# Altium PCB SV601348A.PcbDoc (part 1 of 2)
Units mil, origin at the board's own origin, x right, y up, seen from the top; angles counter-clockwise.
Board outline 3650 x 3650 mil, 6 copper layers (Top Layer, MidLayer1, MidLayer2, MidLayer3, MidLayer4, Bottom Layer), stack 60.8 mil thick; 122 components, 45 nets, 333 pads, 436 vias.
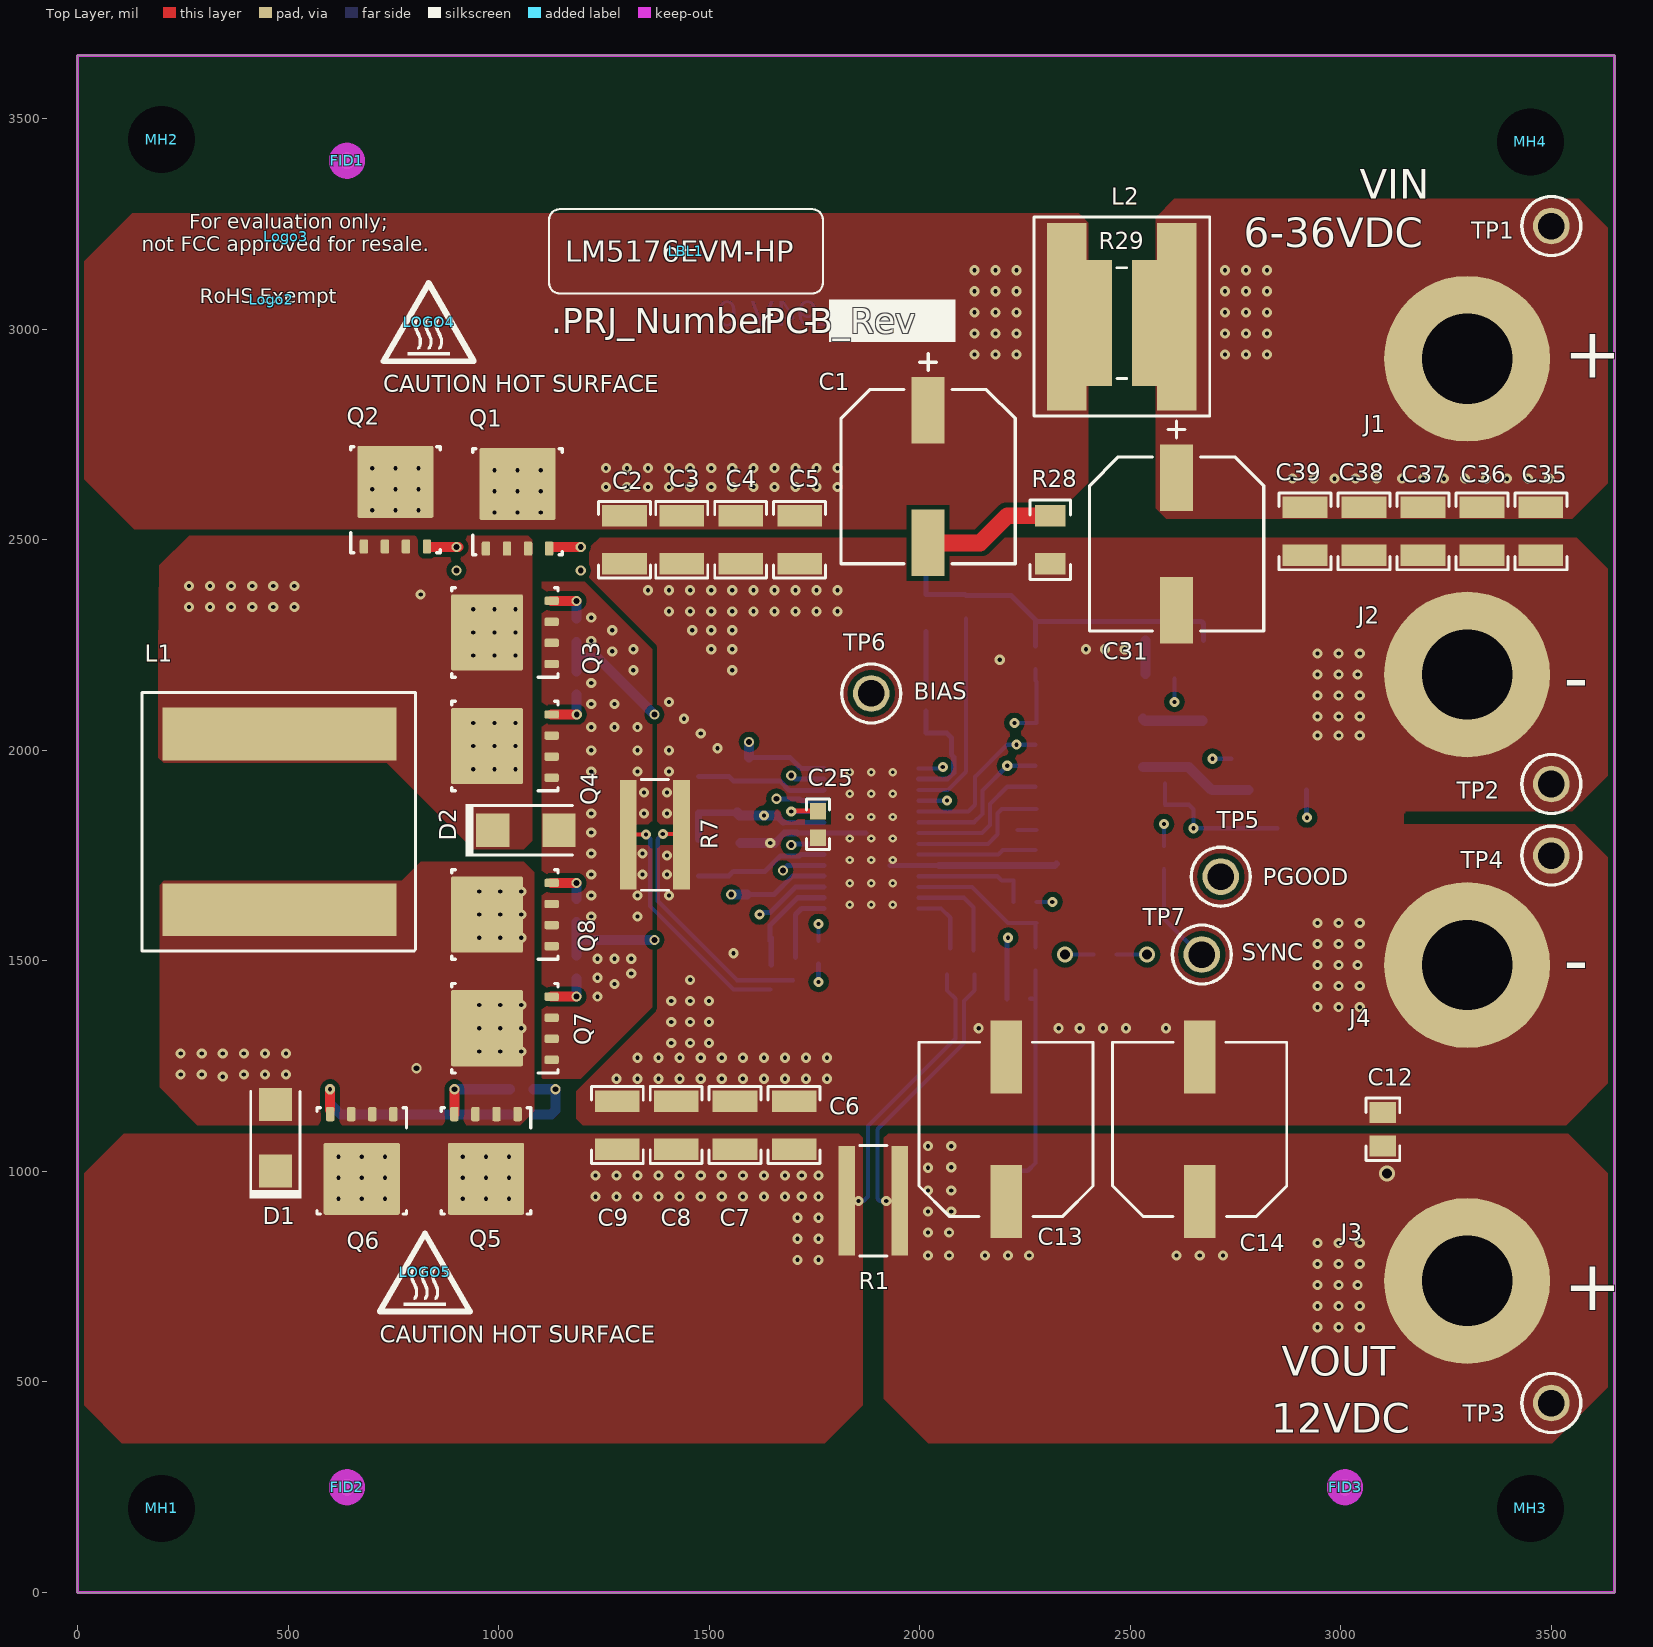
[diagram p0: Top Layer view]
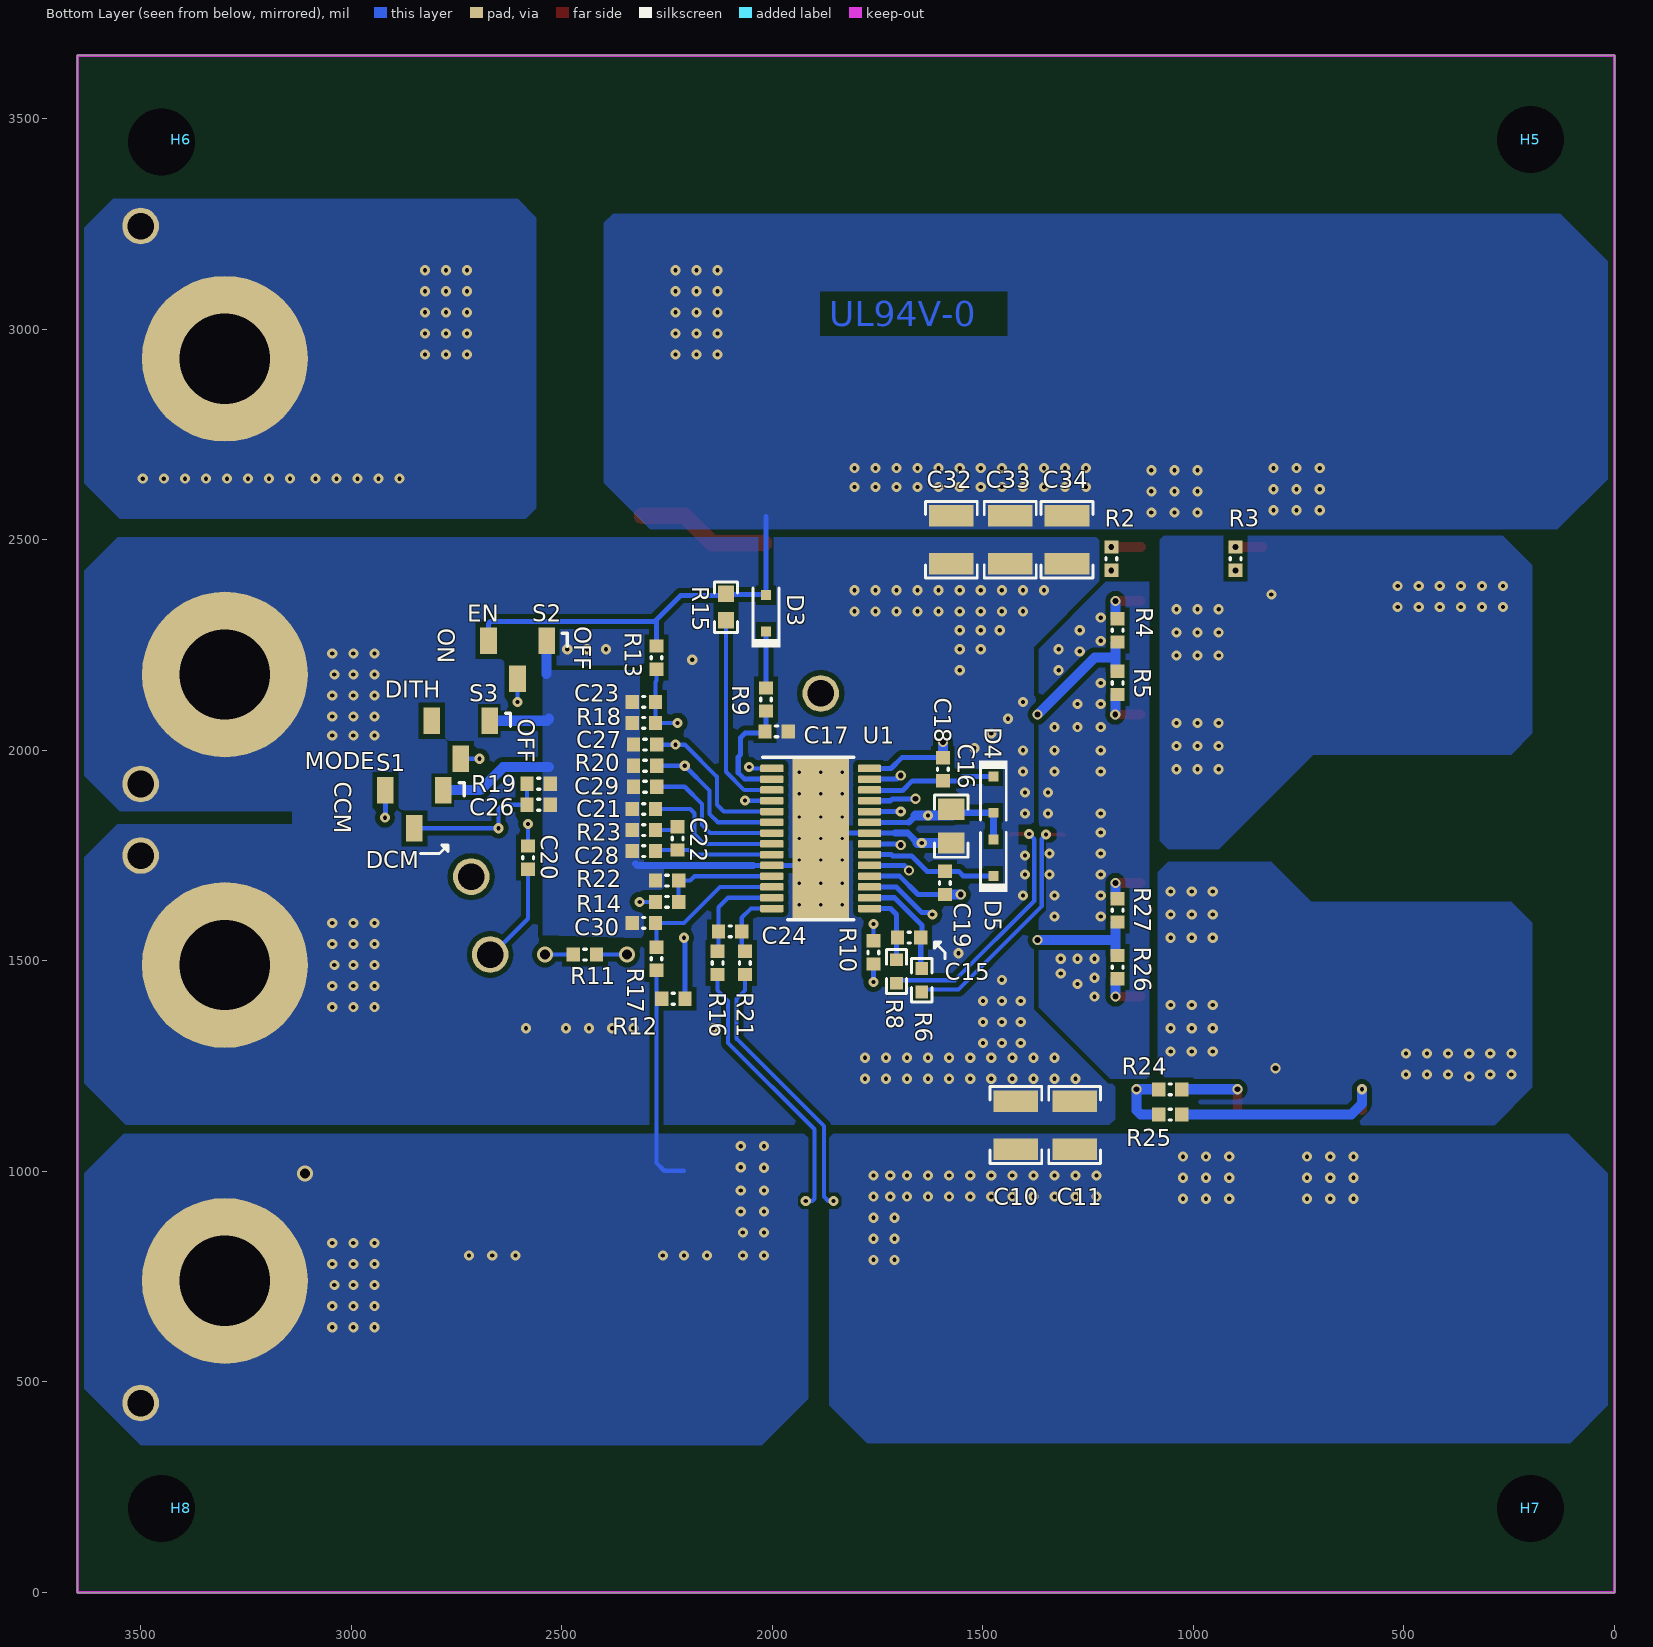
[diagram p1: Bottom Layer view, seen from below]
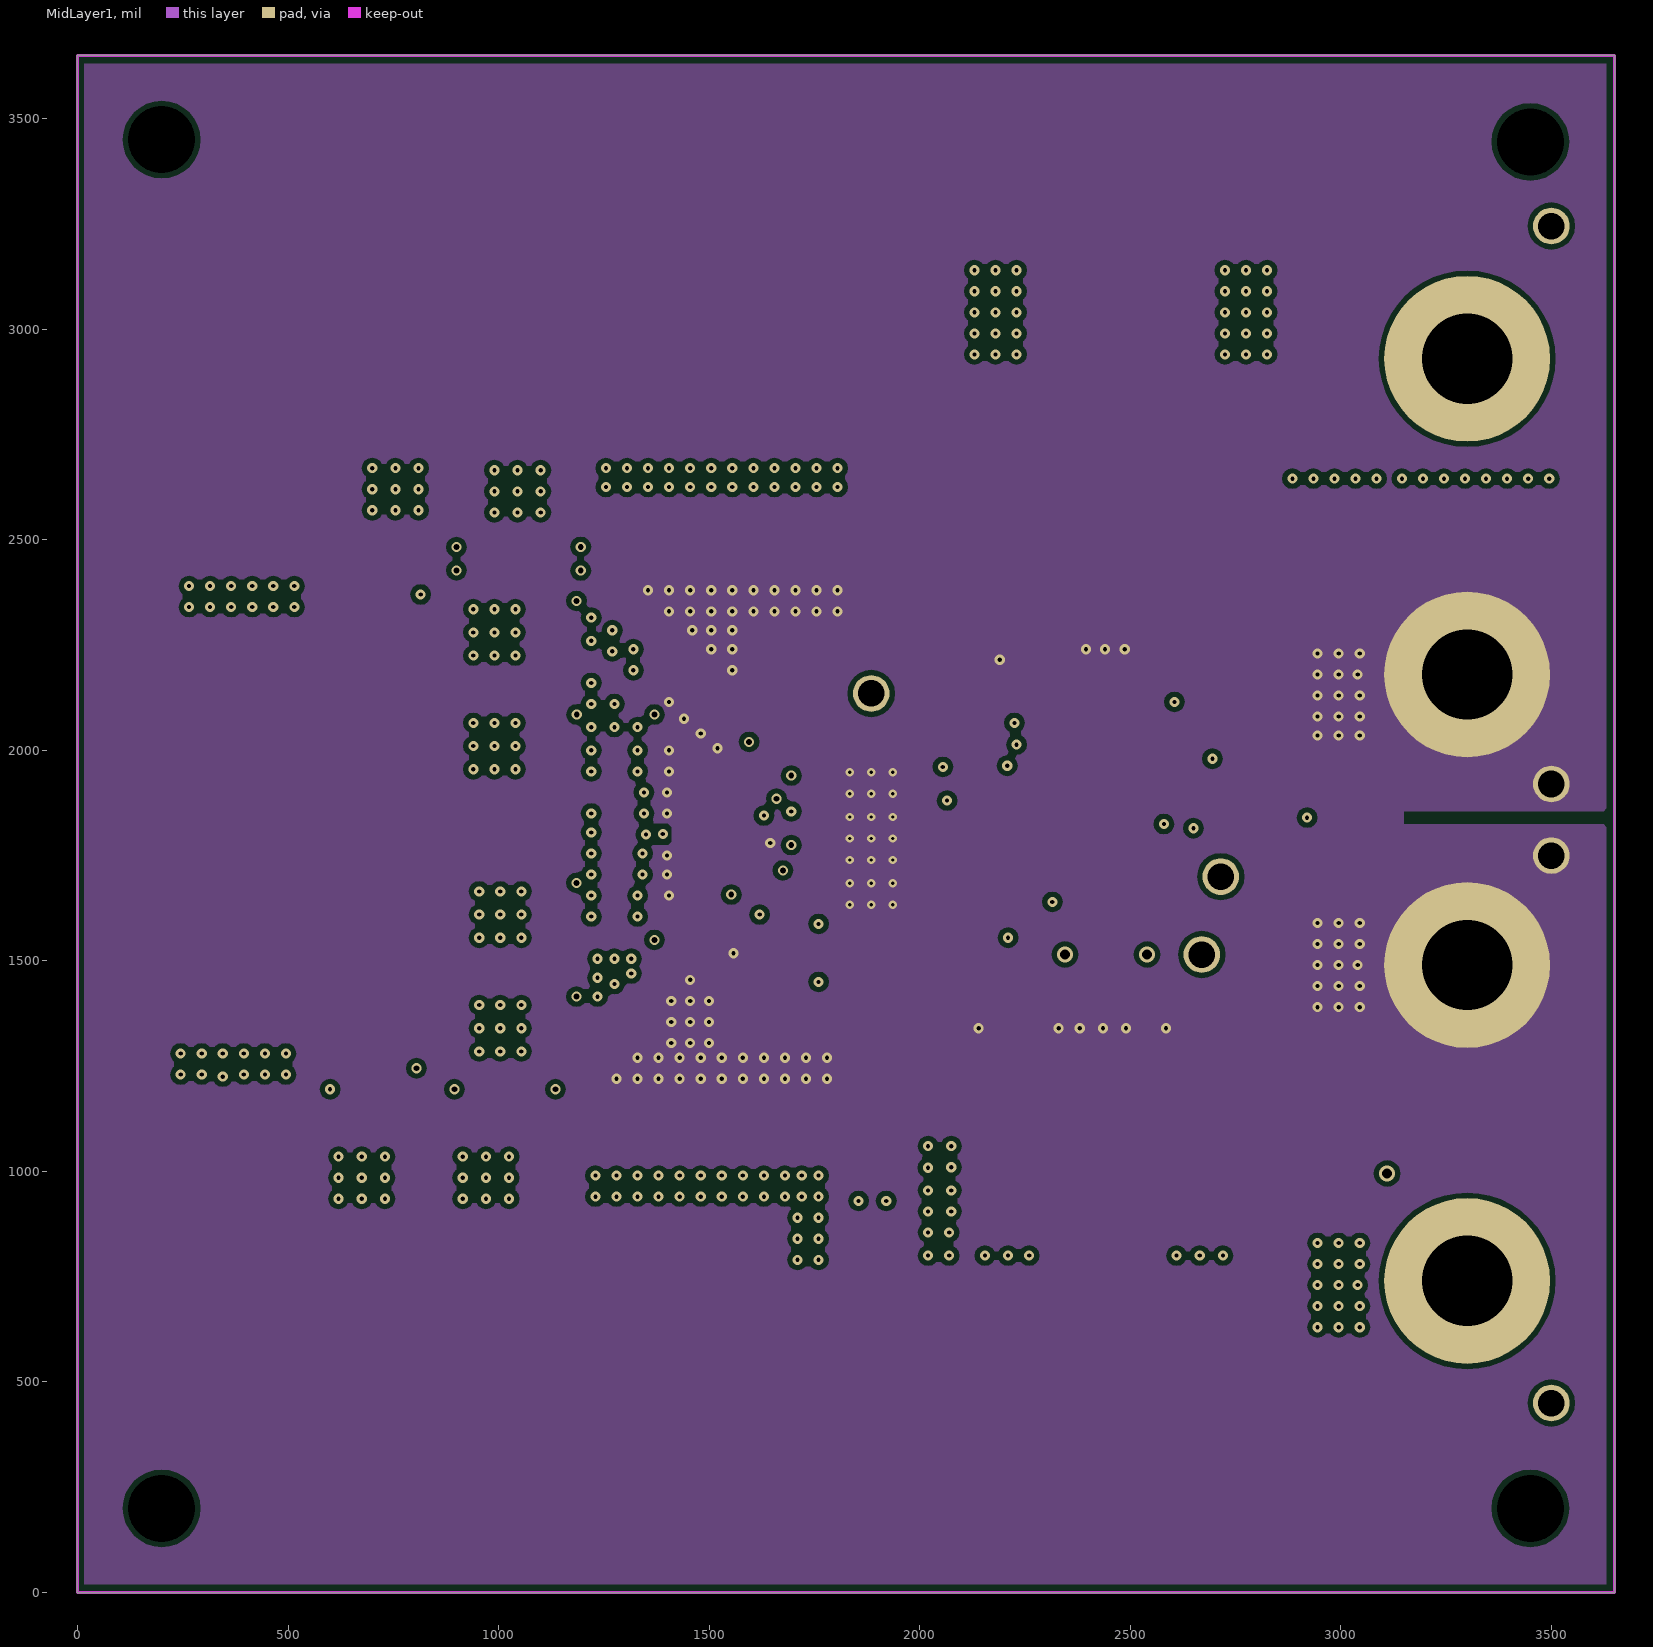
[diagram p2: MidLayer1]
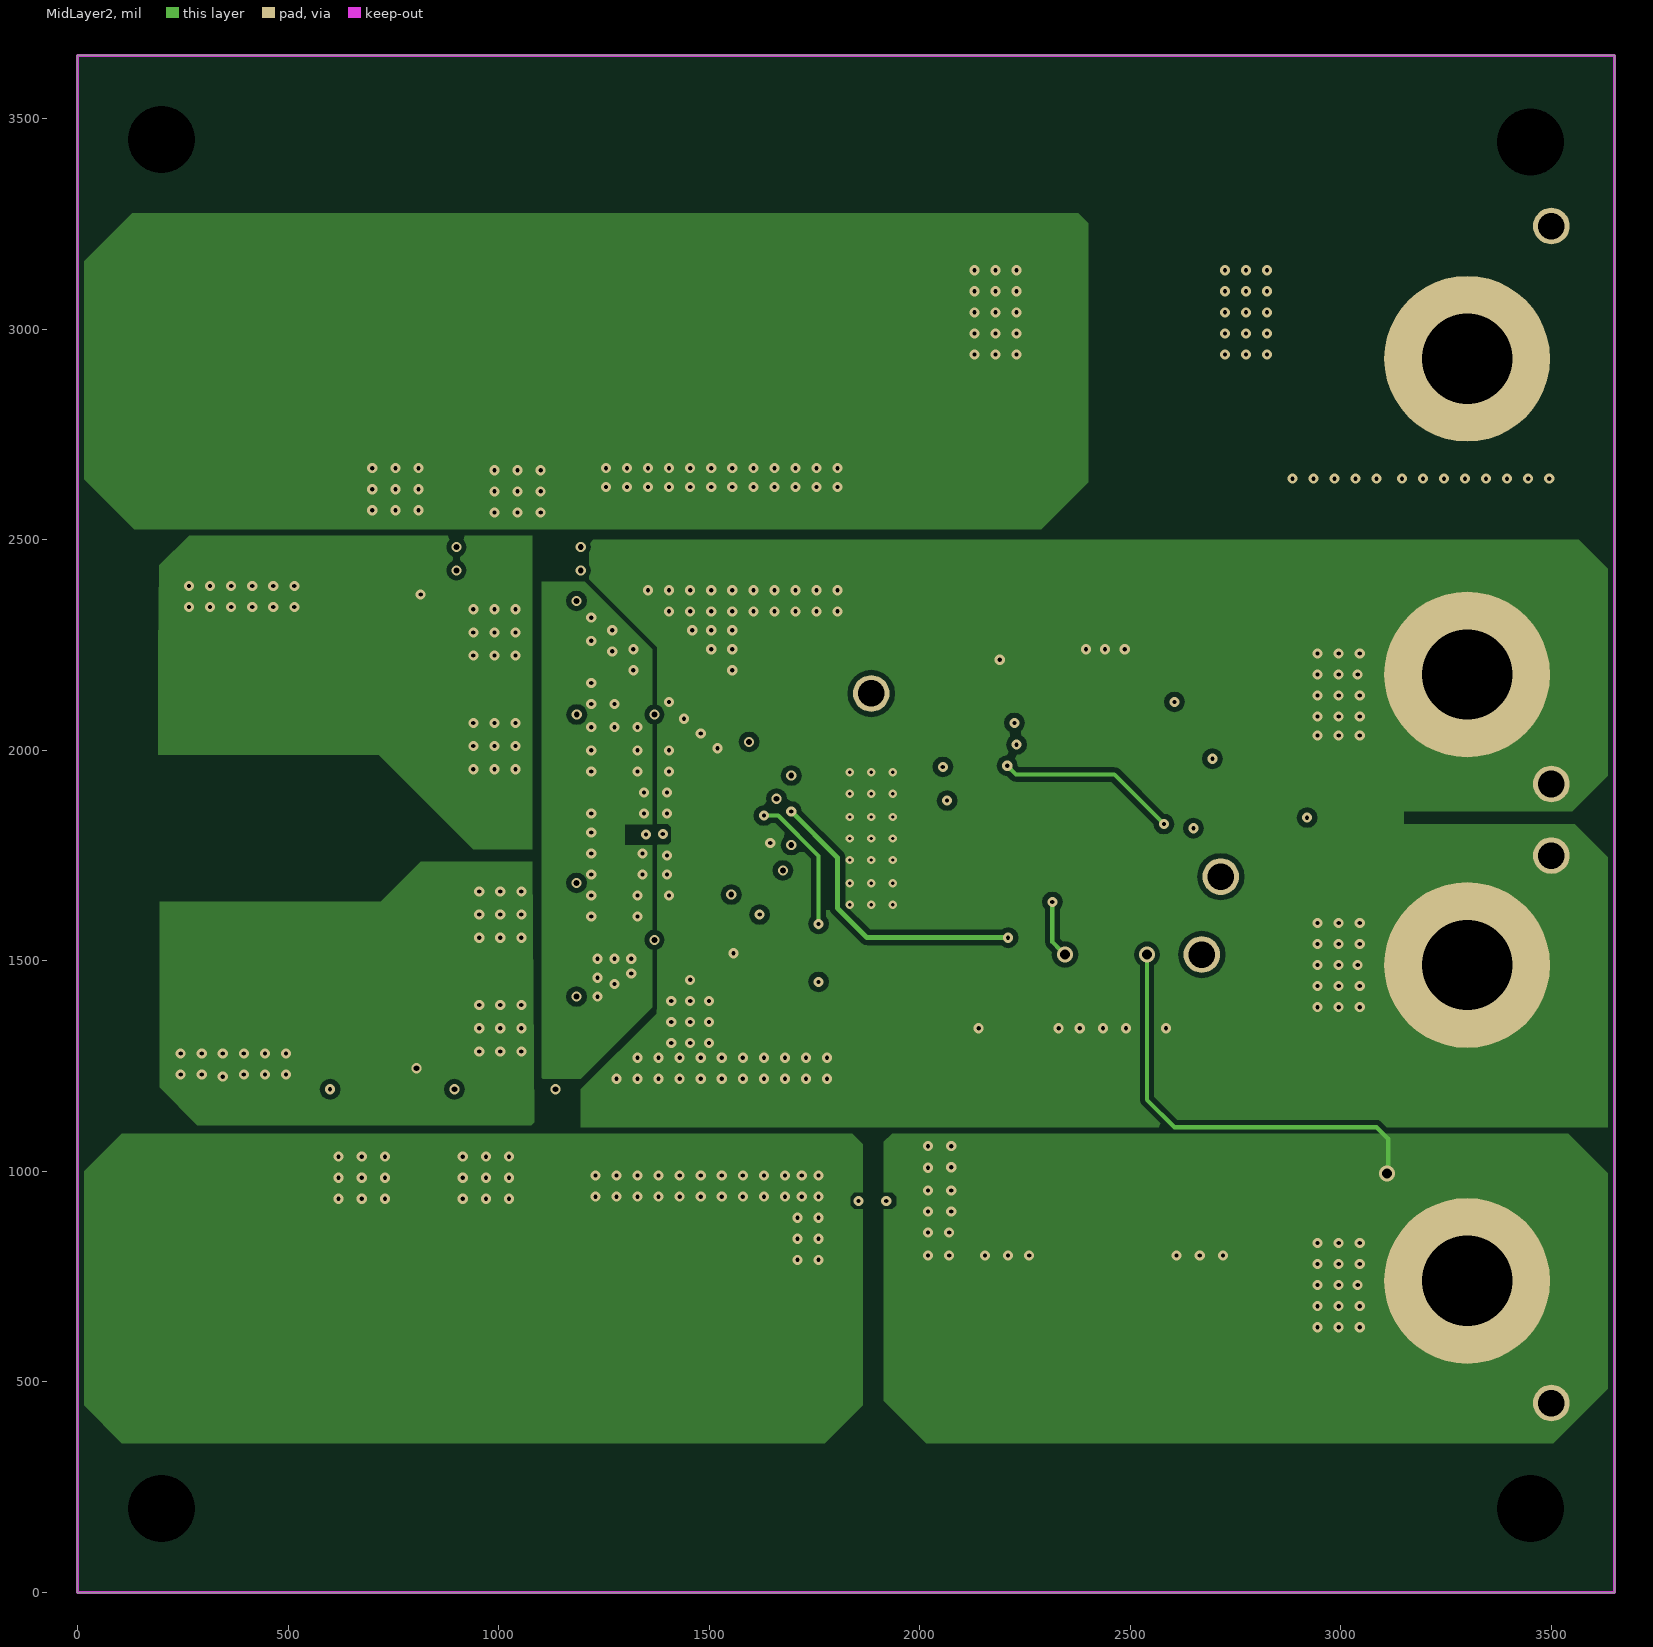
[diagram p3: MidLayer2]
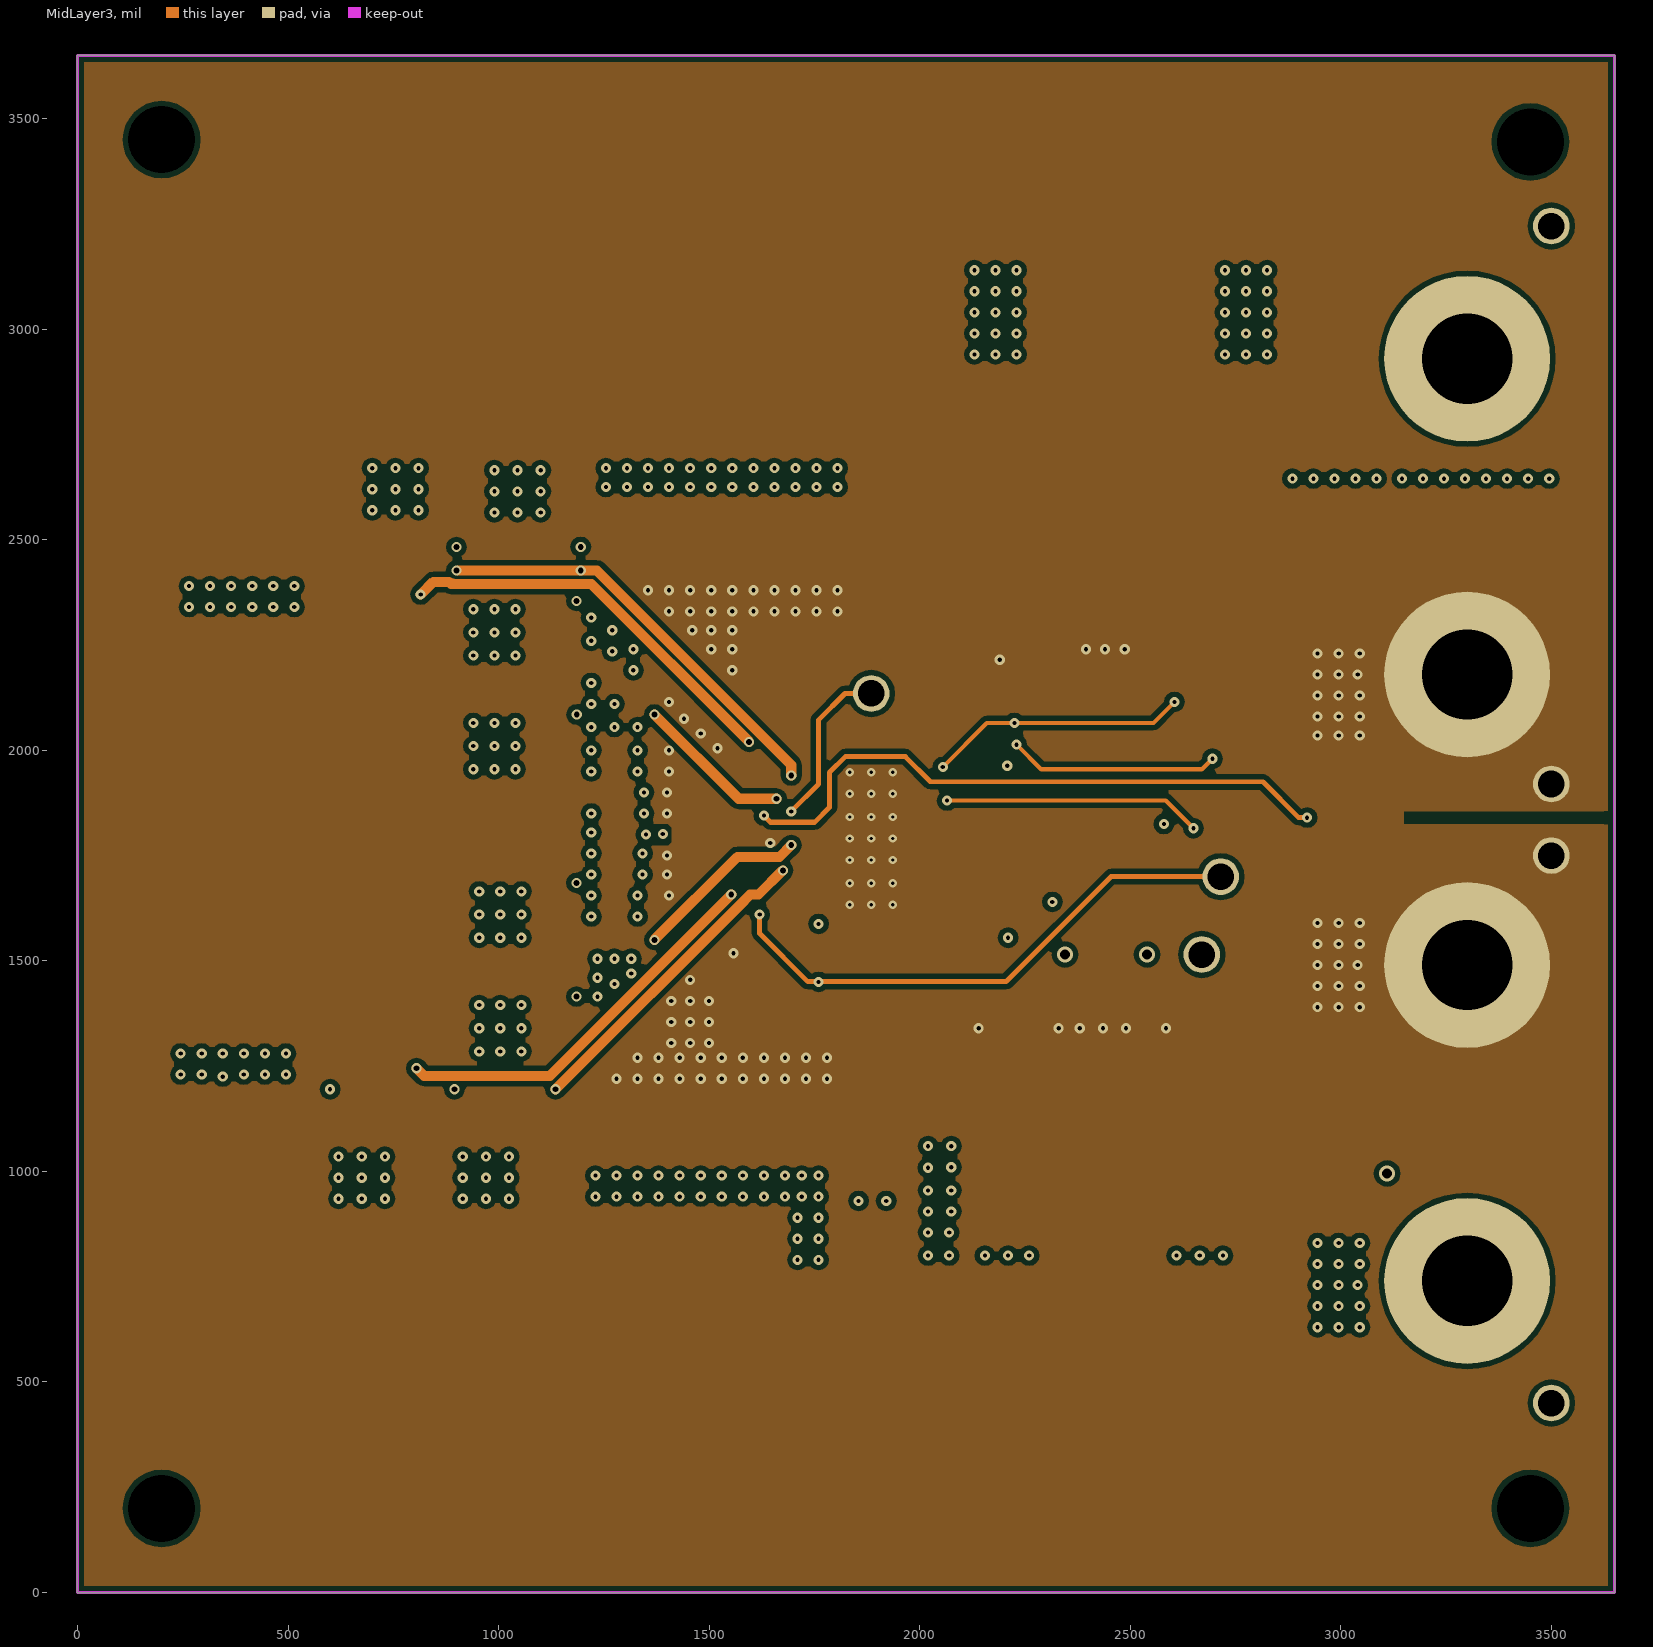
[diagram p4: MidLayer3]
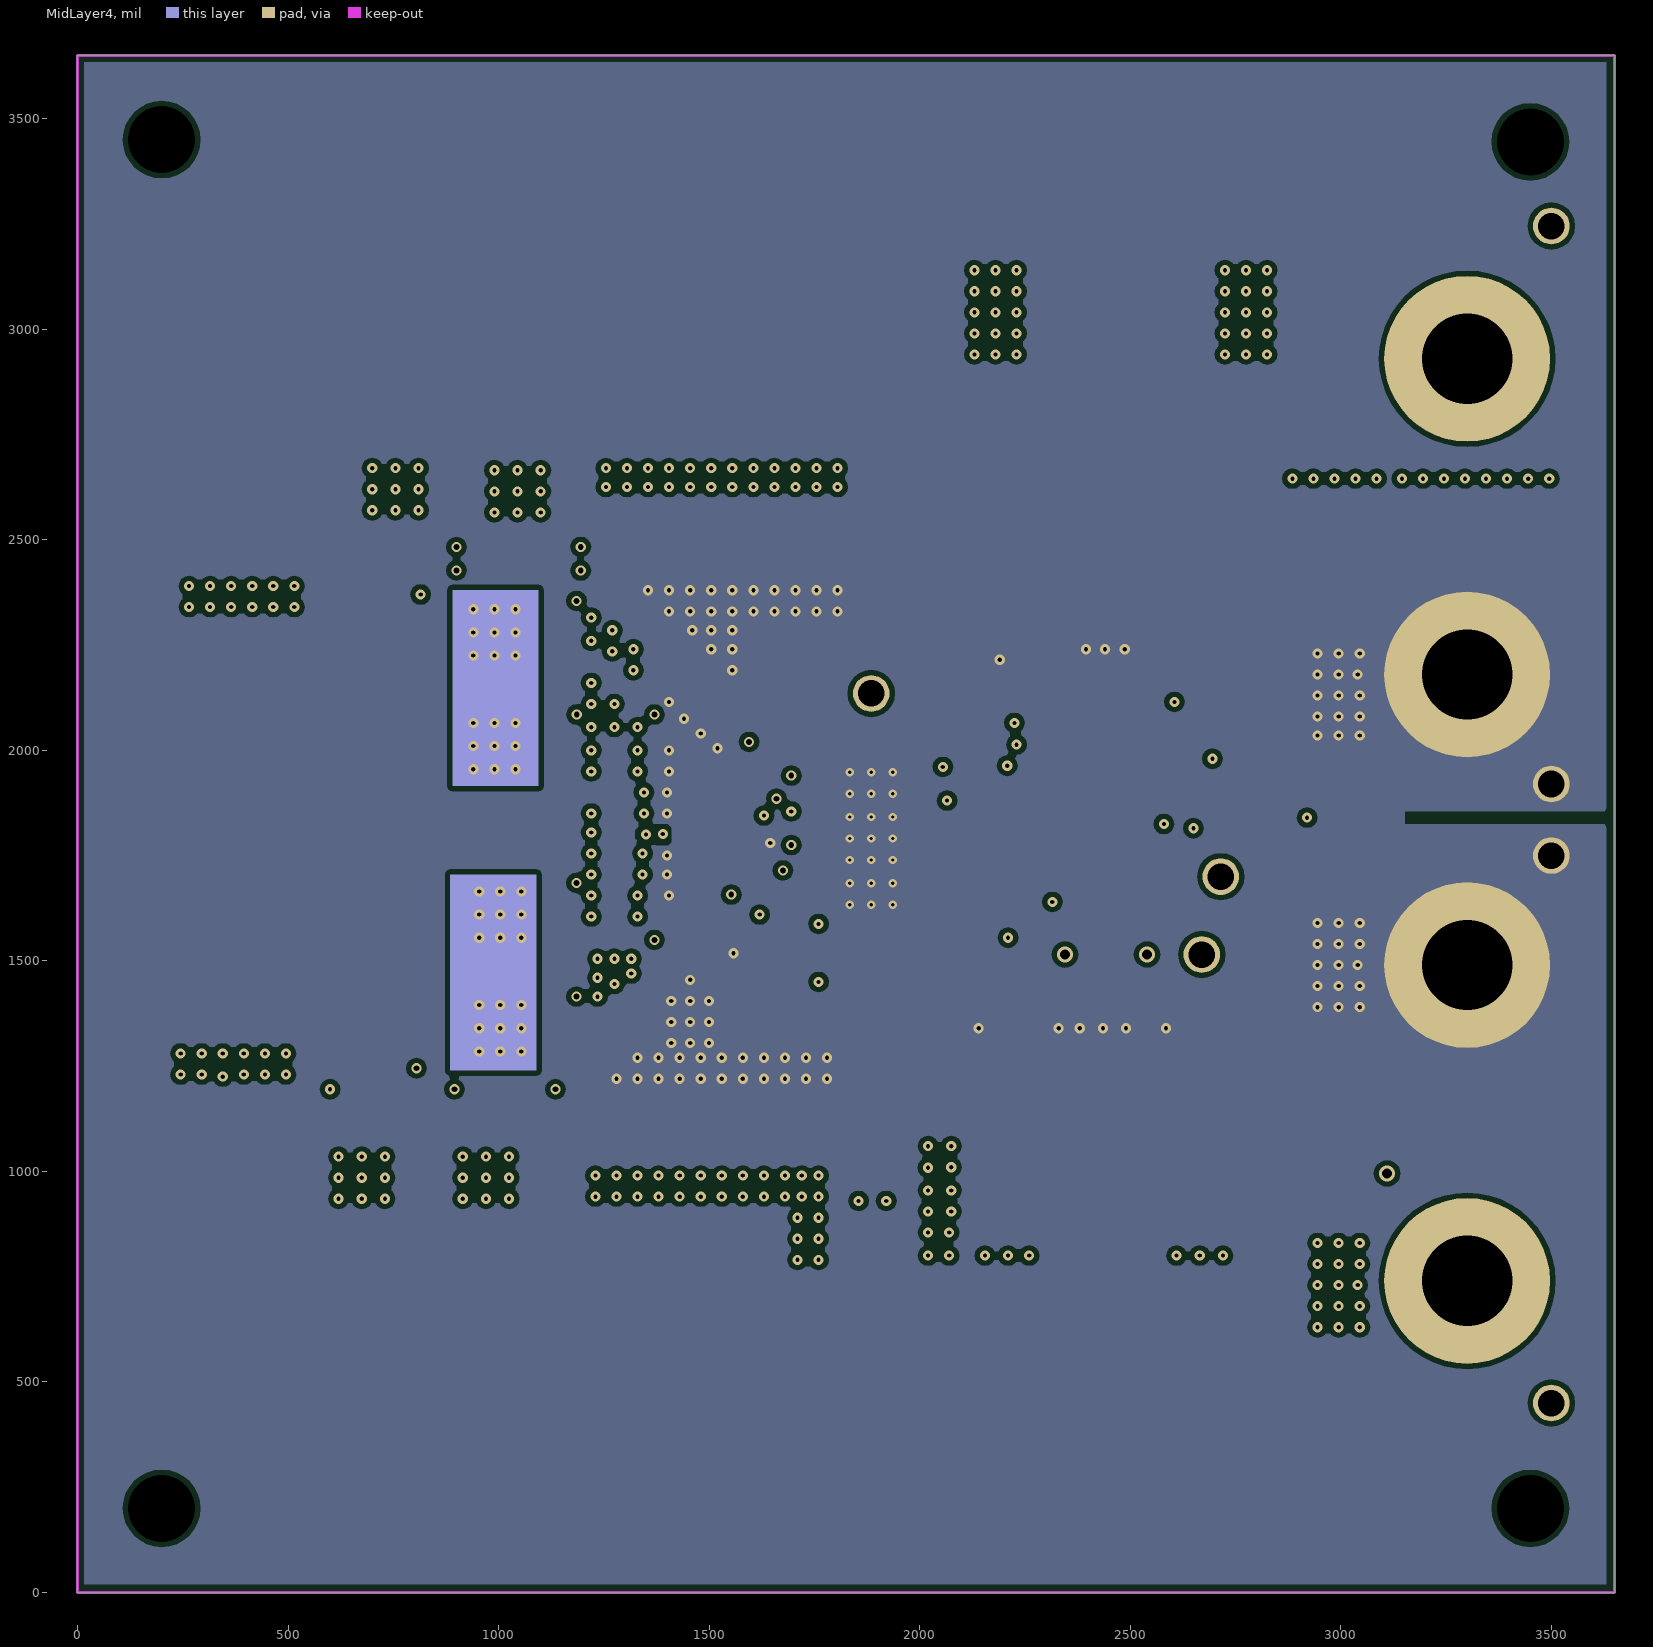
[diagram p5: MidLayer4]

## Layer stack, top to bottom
Top Solder: solder mask 0.4, Solder Resist, Dk 3.5
Top Layer: signal copper 2.8
Dielectric1: prepreg 8, FR-4, Dk 4.2
MidLayer1: signal copper 2.8
Dielectric2: prepreg 8, FR-4, Dk 4.8
MidLayer2: signal copper 2.8
Dielectric3: prepreg 12, FR-4, Dk 4.2
MidLayer3: signal copper 2.8
Dielectric4: prepreg 8, FR-4, Dk 4.8
MidLayer4: signal copper 2.8
Dielectric5: core 8, FR-4, Dk 4.8
Bottom Layer: signal copper 2.8
Bottom Solder: solder mask 0.4, Solder Resist, Dk 3.5

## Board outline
0,0 3650,0 3650,3650 0,3650

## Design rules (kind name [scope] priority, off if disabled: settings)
AcuteAngle [All] p1: minimum=4.50000000000000E+0001 checktracksonly=FALSE
AssemblyTestPointUsage [All] p1: valid=2
Clearance Clearance_BoardEdge_MountingHoles [OnCopper and InComponentClass('Mounting Holes') vs KeepOut] p1: gap=40
Clearance Clearance_BoardEdge_Poly [OnCopper and InPoly vs KeepOut] p2: gap=25
Clearance Clearance_BoardEdge [OnCopper and Not InComponentClass('Logo') and not InComponentClass('FiducialMark') and not InRegion(1000,500,4000,800) and Not IsKeepout vs KeepOut] p3: gap=47
Clearance Clearance_Poly [InPolygon] p4: gap=12
Clearance [All] p5: gap=7.87
ComponentClearance ComponentClearance_EMI-Shunt [InComponent('L2') vs InComponent('R29')] p1: gap=0 collisioncheckmode=3 verticalgap=0 showdistances=FALSE
ComponentClearance ComponentClearance_Shunt [InComponentClass('Header') vs InComponentClass('Shunt')] p2: gap=0 collisioncheckmode=3 verticalgap=0 showdistances=FALSE
ComponentClearance ComponentClearance_MountingHoles_FiducialMarks [InComponentClass('Mounting Holes') vs InComponentClass('FiducialMark')] p3: gap=42 collisioncheckmode=3 verticalgap=10 showdistances=FALSE
ComponentClearance ComponentClearance_Logo [InComponentClass('Logo')] p4: gap=50 collisioncheckmode=3 verticalgap=10 showdistances=FALSE
ComponentClearance ComponentClearance_ScrewToNut [(HasFootprint('NY PMS 440 0025 PH')) vs (HasFootprint('Keystone_1902C'))] p5: gap=5 collisioncheckmode=3 verticalgap=10 showdistances=FALSE
ComponentClearance ComponentClearance_MountingHoles [InComponentClass('Mounting Holes')] p6: gap=200 collisioncheckmode=3 verticalgap=100000 showdistances=FALSE
ComponentClearance ComponentClearance_SmallPassives [HasFootprint('0201*') or HasFootprint('0402*') or HasFootprint('0508') or HasFootprint('0603*') or HasFootprint('0612') or HasFootprint('0805*') or HasFootprint('0815*') or HasFootprint('0830*') or HasFootprint('1206*') or HasFootprint('1210*') or HasFootprint('1808*') or HasFootprint('1812*') or HasFootprint('1825*') or HasFootprint('2010*') or HasFootprint('2220*') or HasFootprint('2225*') or HasFootprint('2512*') or HasFootprint('2728*') or HasFootprint('3518*') vs HasFootprint('0201*') or HasFootprint('0402*') or HasFootprint('0508') or HasFootprint('0603*') or HasFootprint('0612') or HasFootprint('0805*') or HasFootprint('0815*') or HasFootprint('0830*') or HasFootprint('1206*') or HasFootprint('1210*') or HasFootprint('1808*') or HasFootprint('1812*') or HasFootprint('1825*') or HasFootprint('2010*') or HasFootprint('2220*') or HasFootprint('2225*') or HasFootprint('2512*') or HasFootprint('2728*') or HasFootprint('3518*')] p7: gap=10 collisioncheckmode=3 verticalgap=10 showdistances=FALSE
ComponentClearance ComponentClearance_THtoSMT [IsThruComponent vs IsSMTComponent] p8: gap=40 collisioncheckmode=3 verticalgap=30 showdistances=FALSE
ComponentClearance ComponentClearance_THtoTH [IsThruComponent vs IsThruComponent] p9: gap=25 collisioncheckmode=3 verticalgap=15 showdistances=FALSE
ComponentClearance [All] p10: gap=40 collisioncheckmode=3 verticalgap=10 showdistances=FALSE
DiffPairsRouting [All] p1: maxlimit=100 minlimit=10 mostfreqgap=10 toplayer_minwidth=15 toplayer_maxwidth=15 toplayer_prefwidth=15 midlayer1_minwidth=15 midlayer1_maxwidth=15 midlayer1_prefwidth=15 midlayer2_minwidth=15 midlayer2_maxwidth=15 midlayer2_prefwidth=15 midlayer3_minwidth=15 midlayer3_maxwidth=15 midlayer3_prefwidth=15 midlayer4_minwidth=15 midlayer4_maxwidth=15 midlayer4_prefwidth=15 bottomlayer_minwidth=15 bottomlayer_maxwidth=15 bottomlayer_prefwidth=15 maxuncoupledlength=1000
FabricationTestPointUsage TestPointUsage [All] p1: valid=2 allowmultiple=FALSE
FabricationTestpoint Testpoint [All] p1: side=3 testpointundercomponent=TRUE minsize=40 maxsize=100 preferedsize=60 minholesize=0 maxholesize=40 preferedholesize=32 testpointgrid=1 allowsidetop=TRUE allowsidebottom=TRUE usegrid=TRUE gridtolerance=0.01
FanoutControl Fanout_LCC [IsLCC] p1: bgadir=Out bgaviamode=Centered fanoutstyle=Auto fanoutdirection=Alternating viagrid=1 // Fanout_LCC (Default Rule)
FanoutControl Fanout_BGA [IsBGA] p2: bgadir=Out bgaviamode=Centered fanoutstyle=Auto fanoutdirection=Alternating viagrid=1 // Fanout_BGA (Default Rule)
FanoutControl Fanout_Default [All] p4: bgadir=Out bgaviamode=Centered fanoutstyle=Auto fanoutdirection=Alternating viagrid=1 // Fanout_Default (Default Rule)
FanoutControl Fanout_Small [(CompPinCount < 5)] p5: bgadir=Out bgaviamode=Centered fanoutstyle=Auto fanoutdirection=OutThenIn viagrid=1 // Fanout_Small (Default Rule)
HoleSize [All] p1: absolutevalues=TRUE maxlimit=280 minlimit=7.87 maxpercent=80.000 minpercent=20.000
MinimumAnnularRing MinimumAnnularRing_ThermalPadVias [IsVia and InAnyComponent] p1: minimumring=3.94
MinimumAnnularRing [All] p2: minimumring=5
MinimumSolderMaskSliver MinimumSolderMaskSliver_FET [HasFootprint('DNK0008A')] p1: minsoldermaskwidth=0
MinimumSolderMaskSliver MinimumSolderMaskSliver_Logo [InComponentClass('Logo') vs InComponentClass('Logo')] p2: minsoldermaskwidth=0.7
MinimumSolderMaskSliver [All] p3: minsoldermaskwidth=3.94
PlaneConnect [All] p1: planeconnectstyle=Relief reliefexpansion=10 reliefentries=4 reliefconductorwidth=10 reliefairgap=10
PolygonConnect [All] p1: connectstyle=Direct reliefconductorwidth=10 reliefentries=4 polygonreliefangle="90 Angle" airgapwidth=10
RoutingVias ThermalPadVias [IsVia and InAnyComponent] p1: holewidth=7.87 width=19.68 viastyle="Through Hole" minholewidth=7.87 minwidth=15.75 maxholewidth=12.99 maxwidth=23.62
RoutingVias [All] p2: holewidth=10 width=24 viastyle="Through Hole" minholewidth=7.87 minwidth=13.78 maxholewidth=40 maxwidth=65
SMDToCorner [All] p1: distance=30000
SilkToBoardRegionClearance [NOT ((IsComment OR IsDesignator) AND (Hide <> 'FAIL')) AND NOT InRegion (100,500,4000,800)] p1:
SilkToSilkClearance SilkToSilkClearance_PbFree [HasFootprint('Pb-Free_Overlay_Small')] p1: silktosilkclearance=0
SilkToSilkClearance [All] p2: silktosilkclearance=5
SilkToSolderMaskClearance SilkscreenOverComponentPads [IsPad] p1: minsilkscreentomaskgap=5 clearancetoexposedcopper=TRUE
SolderMaskExpansion [All] p1: expansion=1.97
Width [All] p1: maxlimit=100 minlimit=6 preferedwidth=10 checkconnectedcopper=TRUE
15 further rules are at their usual default settings.

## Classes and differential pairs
component class SV601348A-HW: FID1 FID2 FID3 H5 H6 H7 H8 LBL1 Logo2 Logo3 LOGO4 LOGO5 MH1 MH2 MH3 MH4 ZZ1 ZZ2 ZZ3 ZZ4 ZZ5 ZZ6 ZZ7 ZZ8
component class FiducialMark: FID1 FID2 FID3
component class AssemblyNote: ZZ1 ZZ2 ZZ3 ZZ4 ZZ5 ZZ6 ZZ7 ZZ8
component class Label: LBL1
component class SV601348A: C1 C2 C3 C4 C5 C6 C7 C8 C9 C10 C11 C12 C13 C14 C15 C16 C17 C18 C19 C20 C21 C22 C23 C24 C25 C26 C27 C28 C29 C30 C31 C32 C33 C34 C35 C36 C37 C38 C39 D1 D2 D3 D4 D5 J1 J2 J3 J4 L1 L2 Q1 Q2 Q3 Q4 Q5 Q6 Q7 Q8 R1 R2 R3 R4 R5 R6 R7 R8 R9 R10 R11 R12 R13 R14 R15 R16 R17 R18 R19 R20 R21 R22 R23 R24 R25 R26 R27 R28 R29 S1 S2 S3 TP1 TP2 TP3 TP4 TP5 TP6 TP7 U1

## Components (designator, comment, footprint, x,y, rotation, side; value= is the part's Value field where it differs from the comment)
C1 "PCR1J101MCL1GS" CR_1000x1270 2020,2650 r270 top
C2 "GRM32ER71K475KE14L" 1210_270 1298.7,2500 r270 top
C3 "GRM32ER71K475KE14L" 1210_270 1435,2500 r270 top
C4 "GRM32ER71K475KE14L" 1210_270 1575,2500 r270 top
C5 "GRM32ER71K475KE14L" 1210_270 1715,2500 r270 top
C6 "GRM32ER71E226KE15L" 1210_270 1701.85,1110 r90 top
C7 "GRM32ER71E226KE15L" 1210_270 1561.54,1110 r90 top
C8 "GRM32ER71E226KE15L" 1210_270 1421.85,1110 r90 top
C9 "GRM32ER71E226KE15L" 1210_270 1281.85,1110 r90 top
C10 "GRM32ER71E226KE15L" 1210_270 1421.85,1110 r90 bottom
C11 "GRM32ER71E226KE15L" 1210_270 1281.85,1110 r90 bottom
C12 "GRM219R71E105KA88D" 0805_HV 3100,1100 r90 top
C13 "16SVP330M" SM_RADIAL_10AMM 2205,1100 r90 top
C14 "16SVP330M" SM_RADIAL_10AMM 2665,1100 r90 top
C15 "GRM1885C1H470JA01D" 0603L 1675,1555 r0 bottom
C16 "GRM21BR71C475KA73L" 0805_HV 1575,1820 r90 bottom
C17 "GRM188R72A104KA35D" 0603L 1990,2045 r180 bottom
C18 "GRM188R71E224KA88D" 0603L 1595,1955 r270 bottom
C19 "GRM188R71E224KA88D" 0603L 1590,1685 r270 bottom
C20 "GRM1885C2A101JA01D" 0603L 2580,1745 r90 bottom
C21 "GRM188R72A104KA35D" 0603L 2305,1860.63 r0 bottom
C22 "GRM188R71H333KA61D" 0603L 2225,1790.63 r90 bottom
C23 "47pF" 0603L 2305,2115 r0 bottom
C24 "GRM188R71C334KA01D" 0603L 2100,1570 r180 bottom
C25 "GRM188R71E224KA88D" 0603 1758.62,1824.19 r270 top
C26 "47pF" 0603L 2555,1870.63 r180 bottom
C27 "C0603C223K5RACTU" 0603L 2302.2,2013.43 r0 bottom
C28 "GRM1885C2A102JA01D" 0603L 2305,1760.63 r0 bottom
C29 "GRM1885C1H271JA01D" 0603L 2302.2,1913.43 r0 bottom
C30 "GRM1885C2A101JA01D" 0603L 2305,1590 r0 bottom
C31 "PCR1J101MCL1GS" CR_1000x1270 2610,2490 r270 top
C32 "GRM32ER71K475KE14L" 1210_270 1575,2500 r270 bottom
C33 "GRM32ER71K475KE14L" 1210_270 1435,2500 r270 bottom
C34 "GRM32ER71K475KE14L" 1210_270 1300,2500 r270 bottom
C35 "GRM32ER71K475KE14L" 1210_270 3475,2520 r270 top
C36 "GRM32ER71K475KE14L" 1210_270 3335,2520 r270 top
C37 "GRM32ER71K475KE14L" 1210_270 3195,2520 r270 top
C38 "GRM32ER71K475KE14L" 1210_270 3055,2520 r270 top
C39 "GRM32ER71K475KE14L" 1210_270 2915,2520 r270 top
D1 "20V" SMA 470,1080 r90 top
D2 "60V" SMA 1065,1810 r0 top
D3 "60V" SOD-323F 2015,2325 r90 bottom
D4 "100V" sod-323 1475,1895 r270 bottom
D5 "100V" sod-323 1475,1745 r90 bottom
FID1 "Fiducial" Fiducial10-20 640,3400 r0 top
FID2 "Fiducial" Fiducial10-20 640,250 r0 top
FID3 "Fiducial" Fiducial10-20 3010,250 r0 top
H5 "1902C" Keystone_1902C 200,3450 r180 bottom locked
H6 "1902C" Keystone_1902C 3405,3450 r180 bottom locked
H7 "1902C" Keystone_1902C 200,200 r180 bottom locked
H8 "1902C" Keystone_1902C 3405,200 r180 bottom locked
J1 "575-8" Keystone575-8 3300,2930 r90 top
J2 "575-8" Keystone575-8 3300,2180 r90 top
J3 "575-8" Keystone575-8 3300,740 r90 top
J4 "575-8" Keystone575-8 3300,1490 r90 top
L1 "XAL1510-682MEB" XAL1510 480,1830 r270 top
L2 "XAL1010-222MEB" XAL1010 2480,3030 r180 top
LBL1 "LM5176EVM-HP" Label_650x200 1445,3185 r0 top
Logo2 "EU RoHS Exempt Logo" EURoHS_Exempt_60mil 460,3070 r0 top
Logo3 "FCC disclaimer" FCC_disclaimer_stacked 495,3220 r0 top
LOGO4 "CAUTION HOT SURFACE" IEC_HotSurface_Small 834,3017 r0 top
LOGO5 "CAUTION HOT SURFACE" IEC_HotSurface_Small 825,760 r0 top
MH1 "MTG_NoPads" MTG_159mil 200,200 r0 top
MH2 "MTG_NoPads" MTG_159mil 200,3450 r0 top
MH3 "MTG_NoPads" MTG_159mil 3450,200 r0 top
MH4 "MTG_NoPads" MTG_159mil 3450,3445 r0 top
Q1 "CSD18532Q5B" DNK0008A 1045,2590 r90 top
Q2 "CSD18532Q5B" DNK0008A 755,2595 r90 top
Q3 "CSD18532Q5B" DNK0008A 1015,2280 r180 top
Q4 "CSD18532Q5B" DNK0008A 1015,2010 r180 top
Q5 "CSD17573Q5B" DNK0008A 970,1025 r270 top
Q6 "CSD17573Q5B" DNK0008A 675,1025 r270 top
Q7 "CSD17573Q5B" DNK0008A 1015,1340 r180 top
Q8 "CSD17573Q5B" DNK0008A 1015,1610 r180 top
R1 "KRL6432E-M-R004-F-T1" 2512_WIDE 1890,930 r0 top
R2 "RC0603JR-070RL" 0603L 1195,2455 r270 bottom
R3 "RC0603JR-070RL" 0603L 900,2455 r270 bottom
R4 "RC0603JR-070RL" 0603L 1180,2285 r270 bottom
R5 "RC0603JR-070RL" 0603L 1180,2160 r90 bottom
R6 "RC0603FR-07100RL" 0603_HV 1645,1454 r270 bottom
R7 "KRL6432E-M-R004-F-T1" 2512_WIDE 1371.36,1799.47 r180 top
R8 "RC0603FR-07100RL" 0603_HV 1705,1475 r270 bottom
R9 "RC0603FR-0710RL" 0603L 2015,2120.63 r90 bottom
R10 "RC0603FR-0710KL" 0603L 1760,1520 r90 bottom
R11 "RC0603FR-0710RL" 0603L 2445,1515 r180 bottom
R12 "RC0603JR-070RL" 0603L 2235,1410 r180 bottom
R13 "RC0603FR-07249KL" 0603L 2275,2220 r90 bottom
R14 "RC0603FR-07280KL" 0603L 2250,1640 r0 bottom
R15 "CRCW06032K00FKEA" 0603 2110,2340 r90 bottom
R16 "100" 0603L 2130,1495 r270 bottom
R17 "RC0603JR-070RL" 0603L 2275,1505 r90 bottom
R18 "RC0603FR-0759KL" 0603L 2305,2065 r180 bottom
R19 "RC0603FR-0793K1L" 0603L 2555,1920.63 r0 bottom
R20 "CRCW060333K2FKEA" 0603L 2302.2,1963.43 r180 bottom
R21 "100" 0603L 2065,1495 r270 bottom
R22 "RC0603FR-0720KL" 0603L 2249.94,1690.63 r180 bottom
R23 "CRCW06036K19FKEA" 0603L 2305,1810.63 r180 bottom
R24 "RC0603JR-070RL" 0603L 1055,1195 r0 bottom
R25 "RC0603JR-070RL" 0603L 1055,1135 r0 bottom
R26 "RC0603JR-070RL" 0603L 1180,1485 r90 bottom
R27 "RC0603JR-070RL" 0603L 1180,1620 r270 bottom
R28 "CRCW12060000Z0EA" 1206 2310,2500 r90 top
R29 "RCL12250000Z0EG" 2512_WIDE_VISHAY 2480,3015 r180 top
S1 "CJS-1201TA" SW_CJS_1201A 2850,1860 r0 bottom
S2 "CJS-1201TA" SW_CJS_1201A 2605,2215 r0 bottom
S3 "CJS-1201TA" SW_CJS_1201A 2740,2025 r0 bottom
TP1 "5005" Keystone5005 3500,3245 r90 top
TP2 "5006" Keystone5006 3500,1920 r90 top
TP3 "5005" Keystone5005 3500,450 r90 top
TP4 "5006" Keystone5006 3500,1750 r90 top
TP5 "PGOOD" Keystone5007 2715,1700 r90 top
TP6 "BIAS" Keystone5007 1885,2135 r90 top
TP7 "SYNC" Keystone5007 2670,1515 r90 top
U1 "LM5176PWPR" PWP0028C_N 1885,1790.63 r180 bottom
ZZ1 "This Assembly Note is for PCB labels only" AssemblyNoteLabel -95,4653 r0 top
ZZ2 "These assemblies are ESD sensitive, ESD precautions shall be observed." AssemblyNote -95,4547.86 r0 top
ZZ3 "These assemblies must be clean and free from flux and all contaminants. Use of no clean flux is not acceptable." AssemblyNote -95,4463.05 r0 top
ZZ4 "These assemblies must comply with workmanship standards IPC-A-610 Class 2, unless otherwise specified." AssemblyNote -95,4378.24 r0 top
ZZ5 "Remove Kapton tape from switches S1 thru S3 on PCB Bottom side after final wash." AssemblyNote -95,4293.43 r0 top
ZZ6 "Set S1 switch to 'CCM' position as per silkscreen label" AssemblyNote -95,4208.62 r0 top
ZZ7 "Set S2 switch to Center position" AssemblyNote -95,4123.81 r0 top
ZZ8 "Set S3 switch to 'OFF' position per silk screen label." AssemblyNote -95,4039 r0 top

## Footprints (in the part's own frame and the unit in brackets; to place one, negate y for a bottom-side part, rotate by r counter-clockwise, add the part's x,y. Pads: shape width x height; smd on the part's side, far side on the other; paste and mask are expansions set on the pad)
0603 [mm] "0603 from SM-752 data"
  rect 1x0.95 smd: 1(-0.8,0) 2(0.8,0)
  silkscreen extent -1.52,-0.69 1.52,0.69, body extent -0.87,-0.47 0.87,0.47, height 1
0603_HV [mil] "Ernesto recommended land pattern.  26 mil between pads."
  rect 30x30 smd: 1(-28,0) 2(28,0)
  silkscreen extent -52,-24 52,24, body extent -34,-19 34,19, height 39
0603L [mm] "0603 from SM-752 data"
  rect 0.8x0.85 smd: 1(-0.7,0) 2(0.7,0)
  silkscreen extent -0.07,-0.33 0.07,0.33, body extent -0.87,-0.47 0.87,0.47, height 1
0805_HV [mil] "0805 with 30mil clearance between pads"
  rect 50x63 smd: 1(-40,0) 2(40,0)
  silkscreen extent -74,-40 74,40, body extent -43,-29 43,29, height 57
1206 [mm] "1206 from SM-752 data"
  rect 1.3x1.85 smd: 1(-1.45,0) 2(1.45,0)
  silkscreen extent -2.4,-1.21 2.4,1.21, body extent -1.7,-0.9 1.7,0.9, height 1.35
1210_270 [mm] "1210"
  rect 1.3x2.7 smd: 1(-1.45,0) 2(1.45,0)
  silkscreen extent -2.32,-1.57 2.32,1.57, body extent -1.7,-1.35 1.7,1.35, height 2.7
2512_WIDE [mm] "Ohmite recommended land pattern"
  rect 1x6.6 smd: 1(-1.6,0) 2(1.6,0)
  silkscreen extent -0.82,-3.32 0.82,3.35, body extent -1.65,-3.25 1.65,3.25, height 0.7
2512_WIDE_VISHAY [mm] "Vishay recommended land pattern"
  rect 1.9x7.6 smd: 1(-1.55,0) 2(1.55,0)
  silkscreen extent -0.3,-3.32 0.3,3.35, body extent -1.7,-3.25 1.7,3.25, height 0.9
AssemblyNote [mil] "Assembly Note"
AssemblyNoteLabel [mil] "Assembly Note for PCB Labels"
CR_1000x1270 [mm] "SMD, 2-Leads, Dia 10.5mm, Pin Spacing 8mm"
  rect 4x2 smd: 1(-4,0) 2(4,0)
  silkscreen extent -7.4,-5.25 5.25,5.25, body extent -5.25,-5.25 5.25,5.25, height 12.71
DNK0008A [mm] "SON, 8-Leads, Body 5x6mm"
  rrect39% 0.86x0.51 smd paste-0.05 mask-0.05: 1(-2.82,1.905) 2(-2.82,0.635) 3(-2.82,-0.635) 4(-2.82,-1.905) 5(2.82,-1.905) 6(2.82,-0.635) 7(2.82,0.635) 8(2.82,1.905)
  rrect8% 1.48x1.27 on Top Paste: 9(-0.18,1.47) 9(-0.18,0) 9(-0.18,-1.47) 9(1.5,-1.47) 9(1.5,0) 9(1.5,1.47)
  rrect5% 4.34x4.6 smd paste-3 mask-0.05: 9(1.08,0)
  silkscreen extent -3.2,-2.7 3.2,2.7, body extent -3.05,-2.55 3.05,2.55, height 1.06
EURoHS_Exempt_60mil [mil] "EU RoHS Exempt symbol"
FCC_disclaimer_stacked [mil]
Fiducial10-20 [mm]
  round 1 smd mask+0.5: 1(0,0)
  Top Layer keep-out circle w1.178: c0,0 r0.5
IEC_HotSurface_Small [mil]
  silkscreen extent -107,-93 107,92
Keystone575-8 [mm] "Banana Jack"
  round 10 hole 5.45: 1(0,0)
  body extent -3.92,-3.94 3.95,3.94, height 2.36
Keystone5005 [mil] "Keystone Compact loops"
  round 87 hole 63: 1(0,0)
  silkscreen extent -70,-70 70,70, body extent -63,-63 62,63, height 225
Keystone5006 [mil] "Keystone Compact loops"
  round 87 hole 63: 1(0,0)
  silkscreen extent -70,-70 70,70, body extent -63,-63 62,63, height 225
Keystone5007 [mil] "Keystone Compact loops"
  round 87 hole 63: 1(0,0)
  silkscreen extent -70,-70 70,70, body extent -63,-63 62,63, height 225
Keystone_1902C [mil] "Hex Standoff, 4-40 threaded, nylon"
  round 1 on Mech4: 0(0,0)
  body extent -145,-126 146,126, height 501
Label_650x200 [mil] "Thermal Transfer Label"
  round 1 on Mech13: 0(0,0)
  silkscreen extent -325,-100 325,100, body extent -325,-100 325,100, height 1
MTG_159mil [mil] "159mil Non Plated Hole"
  round 150 hole 159 unplated: 1(0,0)
PWP0028C_N [mm] "TSOP, 28-Leads, Body 9.7x4.4mm, Pitch 0.65mm, Exposed Pad, IPC Medium Density"
  rrect22% 1.4x0.45 smd: 1(-2.95,4.225) 2(-2.95,3.575) 3(-2.95,2.925) 4(-2.95,2.275) 5(-2.95,1.625) 6(-2.95,0.975) 7(-2.95,0.325) 8(-2.95,-0.325) 9(-2.95,-0.975) 10(-2.95,-1.625) 11(-2.95,-2.275) 12(-2.95,-2.925) 13(-2.95,-3.575) 14(-2.95,-4.225) 15(2.95,-4.225) 16(2.95,-3.575) 17(2.95,-2.925) 18(2.95,-2.275) 19(2.95,-1.625) 20(2.95,-0.975) 21(2.95,-0.325) 22(2.95,0.325) 23(2.95,0.975) 24(2.95,1.625) 25(2.95,2.275) 26(2.95,2.925) 27(2.95,3.575) 28(2.95,4.225)
  rrect3% 3.4x9.7 smd paste-1.7 mask-1.7: 29(0,0)
  rrect3% 3.1x5.18 on Bottom Paste: 29(0,0)
  rrect3% 3.1x5.18 on Bottom Solder: 29(0,0)
  silkscreen extent -3.5,-4.9 2,4.9, body extent -3.21,-4.85 3.21,4.85, height 0.98
SM_RADIAL_10AMM [mm] "10 x 7.9mm:  Sanyo Oscon F8"
  rect 4.4x1.9 smd: 1(-4.35,0) 2(4.35,0)
  silkscreen extent -5.25,-5.25 5.25,5.25, body extent -5.25,-5.25 5.25,5.25, height 8
SMA [mm] "Molded Diode, 2-Leads, Body 4.3x2.6mm, IPC Medium Density, based on OnSemi component dimensions and land pattern"
  rect 2x2 smd: 1(-2,0) 2(2,0)
  silkscreen extent -3.66,-1.57 2.79,1.57, body extent -2.6,-1.3 2.6,1.3, height 2.42
sod-323 [mm] "NXP recommended land pattern"
  rect 0.6x0.6 smd paste-0.05: 1(-1.1,0) 2(1.1,0)
  silkscreen extent -2.06,-0.86 1.53,0.86, body extent -1.3,-0.67 1.3,0.68, height 1.1
SOD-323F [mm] "NXP recommended land pattern"
  rect 0.6x0.6 smd paste-0.05: 1(-1.1,0) 2(1.1,0)
  silkscreen extent -2.06,-0.86 1.53,0.86, body extent -1.35,-0.67 1.35,0.67, height 0.79
SW_CJS_1201A [mm] "Copal- Electronics"
  rect 1x1.6 smd paste+0 mask+0.05: 1(-1.75,-1.15) 2(0,1.15) 3(1.75,-1.15)
  silkscreen extent -3,-1.6 -2.7,-0.8, body extent -3,-1.55 3,1.55, height 2.51
XAL1010 [mm] "COILCRAFT"
  rect 2.38x11.31 smd: 1(-3.325,0) 2(3.325,0)
  silkscreen extent -5.3,-6 5.3,6, body extent -5.25,-5.9 5.25,5.9, height 10
XAL1510 [mm] "COILCRAFT"
  rect 3.18x14.1 smd: 1(-5.3,0) 2(5.3,0)
  silkscreen extent -7.8,-8.3 7.8,8.2, body extent -7.7,-8.2 7.7,8.2, height 11

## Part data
C1 C31: "CAP, Aluminum Polymer, 100 µF, 63 V, +/- 20%, 0.024 ohm, SMD, 2-Leads, Dia 10.5mm, Pin Spacing 8mm SMD"
C2 C3 C4 C5 C32 C33 C34 C35 C36 C37 C38 C39: "CAP, CERM, 4.7 µF, 80 V, +/- 10%, X7R, 1210"
C6 C7 C8 C9 C10 C11: "CAP, CERM, 22 µF, 25 V, +/- 10%, X7R, 1210"
C12: "CAP, CERM, 1 µF, 25 V, +/- 10%, X7R, 0805"
C13 C14: "CAP, OS-CON, 330 µF, 16 V, +/- 20%, 0.016 ohm, 10x10.3 SMD"
C15: "CAP, CERM, 47pF, 50V, +/-5%, C0G/NP0, 0603"
C16: "CAP, CERM, 4.7 µF, 16 V, +/- 10%, X7R, 0805"
C17 C21: "CAP, CERM, 0.1uF, 100V, +/-10%, X7R, 0603"
C18 C19 C25: "CAP, CERM, 0.22 µF, 25 V, +/- 10%, X7R, 0603"
C20 C30: "CAP, CERM, 100pF, 100V, +/-5%, C0G/NP0, 0603"
C22: "CAP, CERM, 0.033 µF, 50 V, +/- 10%, X7R, 0603"
C23 C26: library part GRM1885C1H470JA01D, "CAP, CERM, 47pF, 50V, +/-5%, C0G/NP0, 0603"
C24: "CAP, CERM, 0.33 µF, 16 V, +/- 10%, X7R, 0603"
C27: "CAP, CERM, 0.022uF, 50V, +/-10%, X7R, 0603"
C28: "CAP, CERM, 1000 pF, 100 V, +/- 5%, C0G/NP0, 0603"
C29: "CAP, CERM, 270 pF, 50 V, +/- 5%, C0G/NP0, 0603"
D1: library part RSX501L-20TE25, "Diode, Schottky, 20 V, 5 A, SMA"
D2: library part RB050L-60TE25, "Diode, Schottky, 60 V, 3 A, SMA"
D3: library part PMEG6010CEJ,115, "Diode, Schottky, 60 V, 1 A, SOD-323F"
D4 D5: library part BAS316,115, "Diode, Ultrafast, 100V, 0.25A, SOD-323"
FID1 FID2 FID3: "Fiducial mark.  There is nothing to buy or mount."
H5 H6 H7 H8: "Standoff, Hex, 0.5\"L #4-40 Nylon"
J1 J2 J3 J4: "Standard Banana Jack, Uninsulated, 8.9mm"
L1: "Inductor, Shielded, Composite, 6.8 µH, 26 A, 0.00417 ohm, SMD"
L2: "Inductor, Shielded, Composite, 2.2 µH, 32 A, 0.00255 ohm, SMD"
LBL1: library part THT-14-423-10, "Thermal Transfer Printable Labels, 0.650\" W x 0.200\" H - 10,000 per roll"
Logo2: library part EURoHS_Exempt
Logo3: library part FCC_disclaimer, "FCC_disclaimer"
LOGO4 LOGO5: library part IEC_HotSurface, "IEC 61010-1 Hot Surface Warning"
MH1 MH2 MH3 MH4: library part "Mounting Hole (non-standard) No Pad", "PCB Mounting Hole, No Pad"
Q1 Q2 Q3 Q4: "MOSFET, N-CH, 60 V, 172 A, DNK0008A (VSON-CLIP-8)"
Q5 Q6 Q7 Q8: "MOSFET, N-CH, 30 V, 100 A, DNK0008A (VSON-CLIP-8)"
R1 R7: "RES, 0.004, 1%, 3 W, 2512 WIDE"
R2 R3 R4 R5 R12 R17 R24 R25 R26 R27: "RES, 0 ohm, 5%, 0.1W, 0603"
R6 R8: "RES, 100 ohm, 1%, 0.1W, 0603"
R9 R11: "RES, 10.0 ohm, 1%, 0.1W, 0603"
R10: "RES, 10.0k ohm, 1%, 0.1W, 0603"
R13: "RES, 249k ohm, 1%, 0.1W, 0603"
R14: "RES, 280k ohm, 1%, 0.1W, 0603"
R15: "RES, 2.00 k, 1%, 0.1 W, 0603"
R16 R21: library part RC0603FR-07100RL, "RES, 100 ohm, 1%, 0.1W, 0603"
R18: "RES, 59.0k ohm, 1%, 0.1W, 0603"
R19: "RES, 93.1 k, 1%, 0.1 W, 0603"
R20: "RES, 33.2 k, 1%, 0.1 W, 0603"
R22: "RES, 20.0k ohm, 1%, 0.1W, 0603"
R23: "RES, 6.19 k, 1%, 0.1 W, 0603"
R28: "RES, 0, 5%, 0.25 W, 1206"
R29: "RES, 0, 5%, 2 W, 2512 WIDE"
S1 S2 S3: "Slide SW, SPDT 0.1A 50VDC"
TP1 TP3: "Test Point, Compact, Red, TH"
TP2 TP4: "Test Point, Compact, Black, TH"
TP5 TP6 TP7: library part 5007, "Test Point, Compact, White, TH"
U1: "55 V Wide VIN Synchronous 4-Switch Buck-Boost Controller, PWP0028C (TSSOP-28)"
ZZ1: library part AssemblyNoteLabel
ZZ2 ZZ3 ZZ4 ZZ5 ZZ6 ZZ7 ZZ8: library part AssemblyNote

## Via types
v1: diameter 24, hole 10, Top Layer to Bottom Layer, tented both sides, 317 vias
v2: diameter 24, hole 10, Top Layer to Bottom Layer, 74 vias
v3: diameter 19.68, hole 7.87, Top Layer to Bottom Layer, tented both sides, 12 vias
v4: diameter 24, hole 14, Top Layer to Bottom Layer, 11 vias
v5: diameter 19.68, hole 7.87, Top Layer to Bottom Layer, 9 vias
v6: diameter 24, hole 14, Top Layer to Bottom Layer, tented both sides, 8 vias
v7: diameter 24, hole 10, Top Layer to Bottom Layer, tented top, 2 vias
v8: diameter 38, hole 24, Top Layer to Bottom Layer, 2 vias
v9: diameter 38, hole 24, Top Layer to Bottom Layer, tented both sides, 1 vias

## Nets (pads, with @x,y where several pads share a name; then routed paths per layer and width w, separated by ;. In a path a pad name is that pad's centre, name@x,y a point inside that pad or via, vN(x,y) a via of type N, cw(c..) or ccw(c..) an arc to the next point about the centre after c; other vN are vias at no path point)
BIAS: C25.1 R12.2 TP6.1 U1.24 | length 1416.3
  Top Layer w12: v1@1695.69,1855.69 C25.1@1758.62,1855.69
  MidLayer2 w12: v1(1695,1855) 1805,1745 1805,1625 1875,1555 v7(2210,1555)
  MidLayer3 w12: v1(1695,1855) 1760,1920 1760,2072.48 1822.52,2135 TP6.1@1885,2135 TP6.1@1885,2160
  Bottom Layer w12: v1@1695.39,1854.61 U1.24@1768.86,1854.61 U1.24@1772.8,1854.61 ; R12.2@2207.44,1410 2207.44,1552.44 v7(2210,1555)
CS: C15.1 R6.1 U1.16 | length 256.8
  Bottom Layer w12: C15.1@1645,1547.44 1645,1585 1709.88,1649.88 U1.16@1772.8,1649.88 ; R6.1@1647.44,1490.44 C15.1@1647.44,1555
CSG: C15.2 R8.1 U1.15 | length 176.2
  Bottom Layer w12: R8.1@1705,1507.56 1705,1610 1719.29,1624.29 U1.15@1772.8,1624.29
DITHER: C27.1 S3.2 U1.5 | length 926.7
  MidLayer3 w10: v1(2230,2013.43) 2288.43,1955 2670,1955 v1(2695,1980)
  Bottom Layer w10: U1.5@1997.2,1854.61 2115.35,1854.61 2131.38,1870.63 2131.38,1937.01 2207.8,2013.43 v1(2230,2013.43) C27.1@2274.64,2013.43 ; v1(2695,1980) S3.2@2740,1980
EN: C23.1 R13.1 R18.2 S2.2 U1.1 | length 908.9
  MidLayer3 w10: v1(2055,1960.63) 2159.37,2065 v1(2225,2065) 2555,2065 v1(2605,2115)
  Bottom Layer w10: U1.1@1997.2,1956.97 2051.34,1956.97 v1(2055,1960.63) ; v1(2225,2065) R18.2@2277.44,2065 C23.1@2277.44,2115 2277.44,2162.56 2275,2165 R13.1@2275,2192.44 ; v1(2605,2115) S2.2@2605,2169.72
FB: R14.1 R22.2 U1.11 | length 280.2
  Bottom Layer w10: U1.11@1997.2,1701.06 2184.57,1701.06 2195,1690.63 R22.2@2222.38,1690.63 R22.2@2222.38,1690.63 R14.1@2222.44,1640
GND: C2.2 C3.2 C4.2 C5.2 C6.2 C7.2 C8.2 C9.2 C10.2 C11.2 C12.2 C13.2 C14.2 C16.1 C17.2 C21.2 C23.2 C25.2 C26.2 C27.2 C28.2 C29.2 C30.2 C31.2 C32.2 C33.2 C34.2 C35.2 C36.2 C37.2 C38.2 C39.2 J2.1 J4.1 R7.1 R8.2 R18.1 R19.1 R20.1 R22.1 R23.1 R28.1 S1.1 S2.1 S3.1 TP2.1 TP4.1 U1.10 U1.22 U1.29@1885,1790.63 | length 1807.8
  Top Layer w10: v1(1390,1801.16) 1432.67,1801.16 R7.1@1434.36,1799.47
  Bottom Layer w10: v1(1390,1801.16) 1377.87,1789.03 1377.87,1642.13 1565.83,1454.17 1624.63,1454.17 ; R8.2@1699.17,1454.17 1665.37,1454.17 ; 1624.67,1454.13 1665.33,1454.13 ; 1624.63,1454.17 1624.67,1454.13 ; 1665.33,1454.13 1665.37,1454.17
  Bottom Layer w12: 1708.43,1803.43 U1.29@1872.2,1803.43 ; U1.29@1930,1726.65 2045,1726.65
  Bottom Layer w16: v1@1655,1780 1678.43,1803.43 1708.43,1803.43 ; 2045,1726.65 2321.02,1726.65 2325,1730.63
  Bottom Layer w24: C16.1@1575,1780 v1(1645,1780) v1@1655,1780 ; 2530,1960 2638.98,1960 2693.7,1905.28 S1.1@2781.1,1905.28 ; 2530,2075 2534.72,2070.28 S3.1@2671.1,2070.28 ; 2536.1,2181.1 S2.1@2536.1,2260.28
  other v1: 1280,1220 1330,1220 1380,1220 1430,1220 1480,1220 1530,1220 1580,1220 1630,1220 1680,1220 1730,1220 1780,1220 1330,1270 1380,1270 1430,1270 1480,1270 1530,1270 1580,1270 1630,1270 1680,1270 1730,1270 1780,1270 1410,1305 1455,1305 1500,1305 2140,1340 2330,1340 2380,1340 2435,1340 2490,1340 2585,1340 1410,1355 1455,1355 1500,1355 2945,1390 2995,1390 3045,1390 1410,1405 1455,1405 1500,1405 2945,1440 2995,1440 3045,1440 1455,1455 2945,1490 2995,1490 3040,1490 1558.01,1518.03 2945,1540 2995,1540 3045,1540 2945,1590 2995,1590 3045,1590 1405,1655 1400,1705 1400,1750 1400,1850 1400,1900 1405,1950 1405,2000 1520,2005 2945,2035 2995,2035 3045,2035 1480,2040 1440,2075 2945,2080 2995,2080 3045,2080 1405,2115 2945,2130 2995,2130 3045,2130 2945,2180 2995,2180 3040,2180 1555,2190 2190,2215 2945,2230 2995,2230 3045,2230 1505,2240 1555,2240 2395,2240 2440,2240 2486.89,2240 1460,2285 1505,2285 1555,2285 1405,2330 1455,2330 1505,2330 1555,2330 1605,2330 1655,2330 1705,2330 1755,2330 1805,2330 1355,2380 1405,2380 1455,2380 1505,2380 1555,2380 1605,2380 1655,2380 1705,2380 1755,2380 1805,2380
  other v3: 1833.82,1633.15 1885,1633.15 1936.18,1633.15 1833.82,1684.33 1885,1684.33 1936.18,1684.33 1833.82,1896.93 1885,1896.93 1936.18,1896.93 1833.82,1948.11 1885,1948.11 1936.18,1948.11
  other v5: 1833.82,1739.45 1885,1739.45 1936.18,1739.45 1833.82,1790.63 1885,1790.63 1936.18,1790.63 1833.82,1841.81 1885,1841.81 1936.18,1841.81
HO1: R2.2 R3.2 U1.27 | length 1088.2
  MidLayer3 w24: v4@905,2427.44 905,2426.95 v4(1195,2426.95) 1233.13,2426.95 1695,1965.08 v6(1695,1940)
  Bottom Layer w12: v6(1695,1940) 1703.62,1931.38 U1.27@1772.8,1931.38
  other v4: 900,2427.44
HO2: R24.2 R25.2 U1.19 | length 1017.1
  MidLayer3 w24: v4(1135.08,1195) 1584.32,1644.24 1584.32,1644.32 1597.44,1657.44 1617.44,1657.44 v6(1675,1715)
  Bottom Layer w12: v6(1675,1715) 1686.65,1726.65 U1.19@1772.8,1726.65
  Bottom Layer w24: R25.2@1082.56,1135 1125,1135 1135.08,1145.08 v4(1135.08,1195) R24.2@1082.56,1195
LO1: R4.2 R5.2 U1.25 | length 798.4
  MidLayer3 w24: v6(1370,2085) 1570,1885 v6(1660,1885)
  Bottom Layer w12: v6(1660,1885) 1660.75,1884.25 1715,1884.25 1719.06,1880.2 U1.25@1772.8,1880.2
  Bottom Layer w24: R5.2@1185,2187.56 1185,2220 ; R4.2@1185,2257.44 1185,2220 ; v6(1370,2085) 1235,2220 1185,2220
LO2: R26.2 R27.2 U1.21 | length 758.1
  MidLayer3 w24: v6@1370,1549.86 1567.01,1746.87 1666.87,1746.87 v6(1695,1775)
  Bottom Layer w12: v6@1697.83,1777.83 U1.21@1772.8,1777.83
  Bottom Layer w24: R26.2@1185,1512.56 1185,1550 ; R27.2@1185,1592.44 1185,1550 ; v6(1370,1550) 1185,1550
MODE: C26.1 R19.2 S1.2 U1.4 | length 1046.7
  MidLayer3 w10: v1(2065,1880.63) 2584.37,1880.63 v1(2650,1815)
  Bottom Layer w10: U1.4@1997.2,1880.2 2064.57,1880.2 v1(2065,1880.63) ; R19.2@2582.56,1920.63 C26.1@2582.56,1870.63 2639.37,1870.63 2650,1860 v1(2650,1815) S1.2@2849.72,1815
NetC1_2: C1.2 R28.2 | length 316.7
  Top Layer w40: C1.2@2020,2492.52 2143.7,2492.52 2208.27,2557.09 R28.2@2310,2557.09
NetC17_1: C17.1 R9.1 U1.2 | length 290.6
  Bottom Layer w12: U1.2@1997.2,1931.38 2065.75,1931.38 2080.87,1946.5 2080.87,1983.93 2075,1989.8 2075,2030.63 2065,2040.63 C17.1@2015,2040.63 ; C17.1@2015,2043.07 R9.1@2015,2093.07
NetC18_2: C18.2 D4.1 U1.26 | length 312.6
  Bottom Layer w12: D4.1@1475,1938.31 1546.69,1938.31 1557.56,1927.44 C18.2@1595,1927.44 1667.56,1927.44 1690.87,1904.13 1771.13,1904.13 U1.26@1772.8,1905.79
NetC19_1: C19.1 D5.1 U1.20 | length 318.7
  Bottom Layer w12: D5.1@1475,1701.69 1546.69,1701.69 1557.56,1712.56 C19.1@1590,1712.56 1632.56,1712.56 1669.13,1749.13 1714.13,1749.13 1717.24,1752.24 U1.20@1772.8,1752.24
NetC20_1: C20.1 TP7.1 | length 241.6
  Bottom Layer w10: C20.1@2580,1717.44 2580,1600 TP7.1@2667.82,1512.18
NetC20_2: C20.2 R20.2 U1.6 | length 847.9
  MidLayer2 w10: v1(2207.8,1963.43) 2228.46,1942.76 2462.24,1942.76 v1(2580,1825)
  Bottom Layer w10: U1.6@1997.2,1829.02 2129.4,1829.02 2149.25,1848.87 2149.25,1904.88 v1(2207.8,1963.43) R20.2@2274.64,1963.43 ; C20.2@2580,1772.56 v1(2580,1825)
NetC21_1: C21.1 U1.8 | length 343.8
  Bottom Layer w10: U1.8@1997.2,1777.83 2162.2,1777.83 2185,1800.63 2185,1850.63 2195,1860.63 C21.1@2277.44,1860.63
NetC22_1: C22.1 C28.1 U1.9 | length 282.3
  Bottom Layer w10: U1.9@1997.2,1752.24 2186.61,1752.24 2197.44,1763.07 C22.1@2225,1763.07 C28.1@2275,1763.07
NetC22_2: C22.2 R23.2 | length 44.9
  Bottom Layer w10: C22.2@2232.56,1810.63 R23.2@2277.44,1810.63
NetC24_1: C24.1 R16.1 U1.13 | length 242.1
  Bottom Layer w10: U1.13@1997.2,1649.88 2105.12,1649.88 2127.56,1627.44 C24.1@2127.56,1570 R16.1@2127.56,1525
NetC24_2: C24.2 R21.1 U1.14 | length 156.8
  Bottom Layer w10: U1.14@1997.2,1624.29 2050.71,1624.29 2072.44,1602.56 C24.2@2072.44,1570 R21.1@2072.44,1530
NetC29_1: C29.1 U1.7 | length 352.3
  Bottom Layer w10: U1.7@1997.2,1803.43 2147.8,1803.43 2167.13,1822.76 2167.13,1872.76 2207.8,1913.43 C29.1@2274.64,1913.43
NetC31_1: C31.1 C35.1 C36.1 C37.1 C38.1 C39.1 J1.1 L2.1 R29.1 TP1.1
  other v1: 2885,2645 2935,2645 2985,2645 3035,2645 3085,2645 3145,2645 3195,2645 3245,2645 3295,2645 3345,2645 3395,2645 3445,2645 3495,2645 2725,2940 2775,2940 2825,2940 2725,2990 2775,2990 2825,2990 2725,3040 2775,3040 2825,3040 2725,3090 2775,3090 2825,3090 2725,3140 2775,3140 2825,3140
NetD2_2: D2.2 Q3.1 Q3.2 Q3.3 Q4.1 Q4.2 Q4.3 Q7.1 Q7.2 Q7.3 Q8.1 Q8.2 Q8.3 R6.2 R7.2 | length 583
  Top Layer w10: R7.2@1308.37,1799.47 1308.9,1800 v1(1350,1800)
  Bottom Layer w10: v1(1350,1800) 1360,1790 1360,1630 1558,1432 R6.2@1645,1432
  other v1: 1235,1415 1275,1445 1235,1460 1315,1470 1235,1505 1275,1505 1315,1505 1220,1605 1330,1605 1220,1655 1330,1655 1220,1705 1342,1705 1220,1755 1342,1755 1220,1805 1220,1850 1345,1850 1345,1900 1220,1950 1330,1950 1220,2000 1330,2000 1220,2055 1275,2055 1330,2055 1220,2110 1275,2110 1220,2160 1320,2190 1270,2235 1320,2240 1220,2260 1270,2285 1220,2315
NetD3_1: D3.1 R9.2 | length 133.5
  Bottom Layer w12: R9.2@2015,2148.19 D3.1@2015,2281.69
NetQ1_4: Q1.4 R2.1 | length 70.7
  Top Layer w24: Q1.4@1124.27,2483.05 v4(1195,2483.05)
NetQ2_4: Q2.4 R3.1 | length 68.8
  Top Layer w24: Q2.4@836.22,2482.56 v4(900,2482.56) v4@905,2482.56
NetQ3_4: Q3.4 R4.1 | length 101.2
  Top Layer w24: Q3.4@1126.22,2355 v4(1185,2355)
  Bottom Layer w24: R4.1@1185,2312.56 v4(1185,2355)
NetQ4_4: Q4.4 R5.1 | length 106.2
  Top Layer w24: Q4.4@1126.22,2085 v4(1185.55,2085)
  Bottom Layer w24: v4@1185,2085.55 R5.1@1185,2132.44
NetQ5_4: Q5.4 R24.1 | length 191.2
  Top Layer w24: Q5.4@895,1136.22 v4(895,1195)
  Bottom Layer w24: v4(895,1195) R24.1@1027.44,1195
NetQ6_4: Q6.4 R25.1 | length 521.6
  Top Layer w24: Q6.4@600,1146.22 v2(600,1195)
  Bottom Layer w24: v2(600,1195) 600,1160 625,1135 R25.1@1027.44,1135
NetQ7_4: Q7.4 R26.1 | length 101.2
  Top Layer w24: Q7.4@1126.22,1415 v4(1185,1415)
  Bottom Layer w24: v4(1185,1415) R26.1@1185,1457.44
NetQ8_4: Q8.4 R27.1 | length 96.2
  Top Layer w24: Q8.4@1126.22,1685 v4(1185,1685)
  Bottom Layer w24: R27.1@1185,1647.56 v4(1185,1685)
NetR10_1: R10.1 TP5.1 U1.17 | length 1513.1
  MidLayer3 w12: v1(1620,1610) 1620,1565 1734.36,1450.64 2205.08,1450.64 2454.45,1700 TP5.1@2715,1700 TP5.1@2715.13,1700
  Bottom Layer w12: v1(1620,1610) 1625,1615 1645,1615 1705.47,1675.47 U1.17@1772.8,1675.47 ; v1(1760,1450) R10.1@1760,1492.44
NetR11_2: R11.2 R14.2 | length 228.2
  MidLayer2 w10: v7(2315,1640) 2315,1545 v8@2335,1525
  Bottom Layer w10: R14.2@2277.56,1640 v7(2315,1640) ; v8(2345,1515) R11.2@2412.44,1515
NetR15_1: R15.1 U1.3 | length 494.2
  Bottom Layer w10: U1.3@1997.2,1905.79 2066.85,1905.79 2110,1948.94 R15.1@2110,2312.44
